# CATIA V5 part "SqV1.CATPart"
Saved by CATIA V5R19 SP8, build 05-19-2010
Part number: SqV1
Publications: "Droite.2", "Plan.1"
Bounding box of the stored display mesh (mm): x 0 to 20, y -30 to 190, z 0 to 0
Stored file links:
  F:\Travail\2e année\IAO\Projetsave\SqV1.CATPart
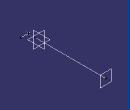
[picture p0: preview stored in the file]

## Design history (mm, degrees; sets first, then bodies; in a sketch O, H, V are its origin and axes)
Set1
  Point1: (0, -30, 0)
  Plane1: type Offset, RefPlane zx-plane, Offset 190
  Line1: type PtDir, LineFirstUpto Plane1, RefPoint Point1, Direction zx-plane, Start 0, End 20
  Line2: type PtDir, RefPoint Point1, Direction yz-plane, Start 0, End 20
Body1 (main body)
